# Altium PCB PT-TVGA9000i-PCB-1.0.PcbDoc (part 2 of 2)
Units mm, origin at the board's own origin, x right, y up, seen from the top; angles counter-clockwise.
Board outline 80.1 x 47 mm, 4 copper layers (Top Layer, Layer 1, Layer 2, Bottom Layer), stack 0.603 mm thick; 67 components, 130 nets, 468 pads, 340 vias.
Unrouted connection lines stored in the file: 9.
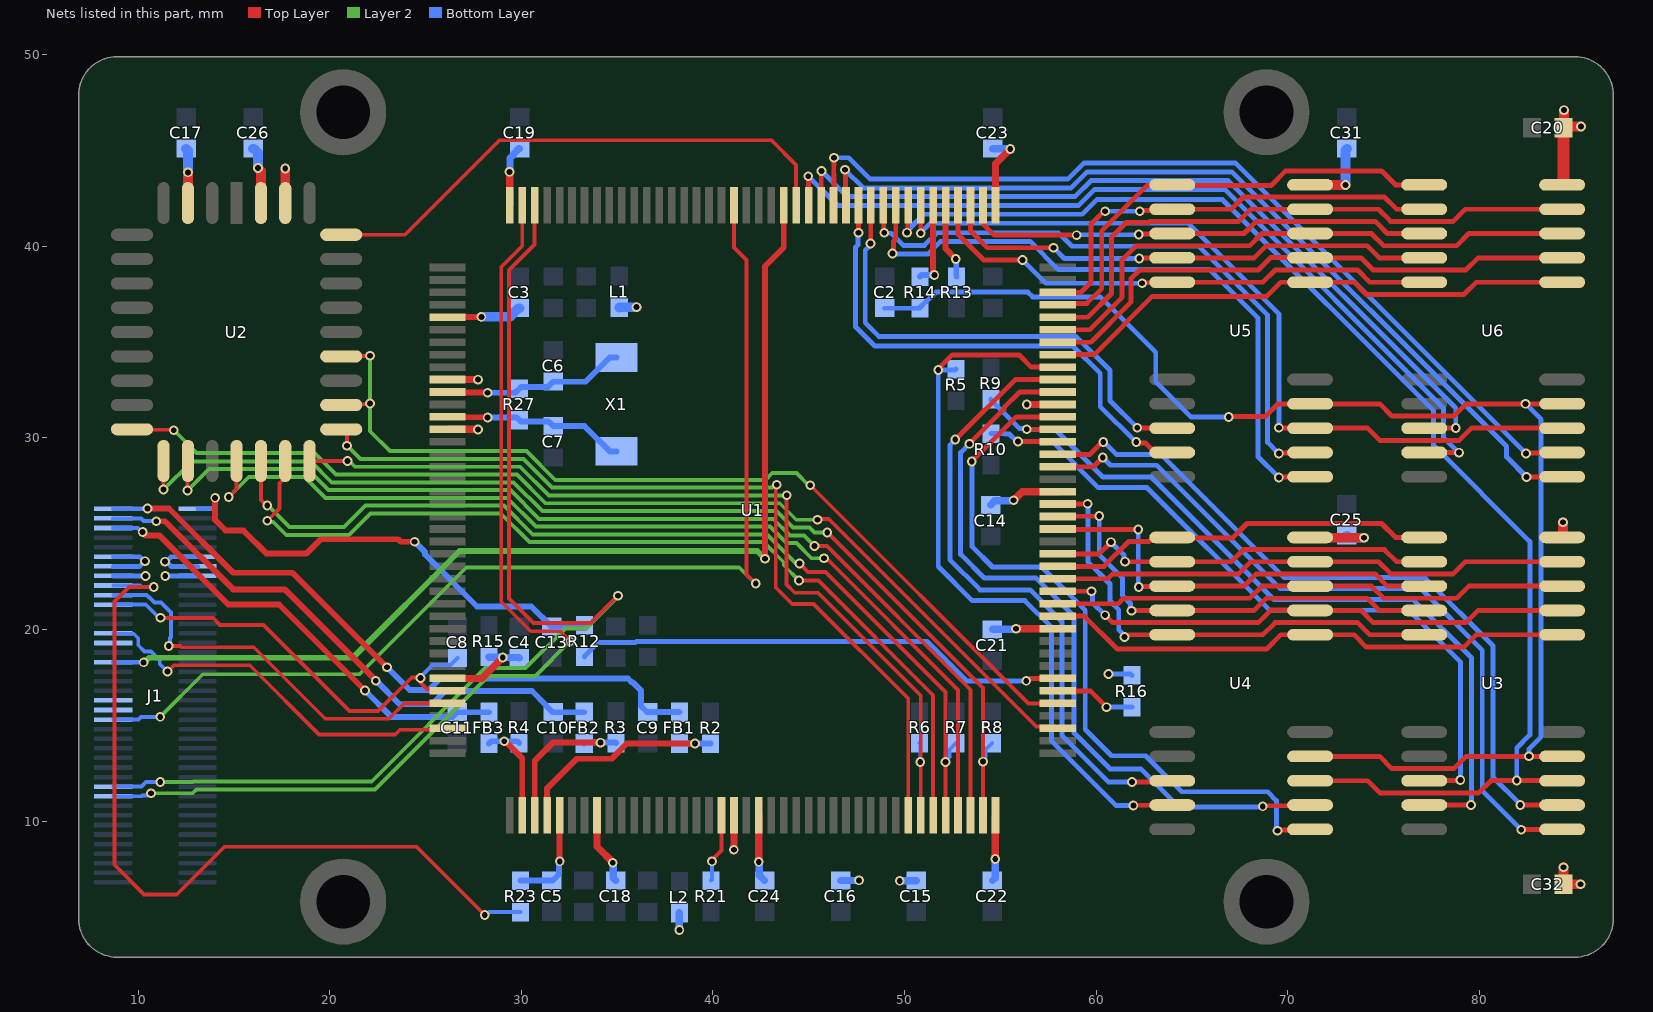
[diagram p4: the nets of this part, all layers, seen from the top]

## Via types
v1: diameter 0.508, hole 0.305, Top Layer to Bottom Layer, tented both sides, 338 vias
v2: diameter 0.7, hole 0.7, Top Layer to Bottom Layer, 2 vias

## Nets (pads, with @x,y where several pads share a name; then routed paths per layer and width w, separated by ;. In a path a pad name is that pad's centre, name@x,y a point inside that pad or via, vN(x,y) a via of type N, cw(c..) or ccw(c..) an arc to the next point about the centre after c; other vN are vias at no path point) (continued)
LA22: J1.21 U1.118 | length 58.4
  Top Layer w0.203: U1.118@30.7,42.15 30.7,40.101 29.362,38.764 29.362,21.618 30.644,20.337 33.621,20.337 v1(35.052,21.768)
  Layer 2 w0.203: v1(11.151,12.04) 12.852,12.04 12.877,12.065 22.197,12.065 28.115,17.983 30.229,17.983 32.299,20.053 33.388,20.053 35.027,21.692 35.027,21.742 v1(35.052,21.768)
  Bottom Layer w0.203: J1.21@8.7,11.8 10.181,11.8 10.42,12.04 v1(11.151,12.04)
LA23: J1.19 U1.119 | length 52.8
  Top Layer w0.203: U1.119@30.05,42.15 30.05,40.026 28.956,38.932 28.956,21.45 30.492,19.914 32.032,19.914 v1(32.552,19.393)
  Layer 2 w0.203: v1(10.668,11.453) 12.84,11.453 13.046,11.659 22.365,11.659 28.283,17.577 30.736,17.577 v1(32.552,19.393)
  Bottom Layer w0.203: J1.19@8.7,11.3 10.189,11.3 10.217,11.328 10.46,11.328 10.586,11.453 v1(10.668,11.453)
MAA0: U1.52 U3.6 U4.6 | length 27.9
  Top Layer w0.254: U1.52@58,20.7 59.397,20.7 61.112,18.985 68.91,18.985 69.654,19.728 U4.6@71.177,19.728 73.475,19.728 74.117,19.086 79.197,19.086 79.839,19.728 U3.6@84.334,19.728
MAA1: U1.54 U3.7 U4.7 | length 28.1
  Top Layer w0.254: U1.54@58,22 58.002,21.998 59.764,21.998 v1(59.766,21.996) ; v1(60.477,20.752) 60.866,20.363 68.46,20.363 69.113,21.017 71.159,21.017 U4.7@71.177,20.998 73.831,20.998 74.466,20.363 79.308,20.363 79.943,20.998 U3.7@84.334,20.998
  Bottom Layer w0.254: v1(59.766,21.996) 59.815,21.948 59.815,21.414 v1(60.477,20.752)
MAA2: U1.53 U3.8 U4.8 | length 27.2
  Top Layer w0.254: U1.53@58,21.35 61.152,21.35 61.435,21.633 68.028,21.633 68.663,22.268 U4.8@71.177,22.268 74.378,22.268 75.013,21.633 78.826,21.633 79.461,22.268 U3.8@84.334,22.268
MAA3: U1.55 U3.9 U4.9 | length 27.2
  Top Layer w0.254: U1.55@58,22.65 60.623,22.65 60.876,22.903 67.444,22.903 68.079,23.538 U4.9@71.177,23.538 74.745,23.538 75.38,22.903 78.645,22.903 79.28,23.538 U3.9@84.334,23.538
MAA4: U1.56 U3.11 U4.11 | length 20.3
  Top Layer w0.254: U1.56@58,23.3 60.409,23.3 61.697,24.587 62.765,24.587 62.986,24.808 U4.11@63.977,24.808 ; U4.11@64.01,24.776 67.118,24.776 67.88,25.538 74.905,25.538 75.634,24.808 U3.11@77.134,24.808
MAA5: U1.57 U3.12 U4.12 | length 20.5
  Top Layer w0.254: U1.57@58,23.95 60.17,23.95 v1(60.782,24.562) ; v1(61.519,23.546) 61.526,23.538 U4.12@63.977,23.538 67.066,23.538 67.701,24.173 75.056,24.173 75.691,23.538 U3.12@77.134,23.538
  Bottom Layer w0.254: v1(60.782,24.562) 61.47,23.874 61.47,23.594 v1(61.519,23.546)
MAA6: U1.59 U3.13 U4.13 | length 22.7
  Top Layer w0.254: U1.59@58,25.25 58.028,25.222 v1(62.205,25.222) ; v1(62.23,22.225) 62.252,22.247 63.956,22.247 U4.13@63.977,22.268 67.723,22.268 68.358,22.903 74.567,22.903 75.202,22.268 U3.13@77.134,22.268
  Bottom Layer w0.254: v1(62.205,25.222) 62.205,22.25 v1(62.23,22.225)
MAA7: U1.60 U3.14 U4.14 | length 23.7
  Top Layer w0.254: U1.60@58,25.9 58.017,25.917 60.156,25.917 v1(60.173,25.933) ; v1(61.849,20.98) 61.858,20.989 63.968,20.989 U4.14@63.977,20.998 68.257,20.998 68.892,21.633 74.161,21.633 74.796,20.998 U3.14@77.134,20.998
  Bottom Layer w0.254: v1(60.173,25.933) 60.173,23.901 61.392,22.682 61.392,21.768 61.8,21.359 61.8,21.029 v1(61.849,20.98)
MAA8: U1.61 U3.15 U4.15 | length 25.5
  Top Layer w0.254: U1.61@58,26.55 58.009,26.559 59.554,26.559 v1(59.563,26.568) ; v1(61.493,19.609) 61.562,19.609 61.682,19.728 U4.15@63.977,19.728 68.714,19.728 69.349,20.363 73.653,20.363 74.288,19.728 U3.15@77.134,19.728
  Bottom Layer w0.254: v1(59.563,26.568) 59.588,26.543 59.588,23.52 60.731,22.377 60.731,21.488 61.189,21.031 61.189,19.982 61.493,19.678 v1(61.493,19.609)
MAB0: U1.73 U5.6 U6.6 | length 28.4
  Top Layer w0.254: U1.73@58,34.35 59.902,34.35 62.941,37.389 68.91,37.389 69.654,38.132 U5.6@71.177,38.132 73.475,38.132 74.117,37.49 79.197,37.49 79.839,38.132 U6.6@84.334,38.132
MAB1: U1.74 U5.7 U6.7 | length 29.4
  Top Layer w0.254: U1.74@58,35 59.74,35 61.824,37.084 61.824,38.317 62.274,38.767 68.46,38.767 69.113,39.421 71.159,39.421 U5.7@71.177,39.402 73.831,39.402 74.466,38.767 79.308,38.767 79.943,39.402 U6.7@84.334,39.402
MAB2: U1.75 U5.8 U6.8 | length 30.1
  Top Layer w0.254: U1.75@58,35.65 59.665,35.65 61.366,37.352 61.366,39.307 62.097,40.037 68.028,40.037 68.663,40.672 U5.8@71.177,40.672 74.378,40.672 75.013,40.037 78.826,40.037 79.461,40.672 U6.8@84.334,40.672
MAB3: U1.76 U5.9 U6.9 | length 30.9
  Top Layer w0.254: U1.76@58,36.3 59.566,36.3 60.808,37.541 60.808,40.488 61.57,41.25 62.761,41.25 62.819,41.307 67.444,41.307 68.079,41.942 U5.9@71.177,41.942 74.745,41.942 75.38,41.307 78.645,41.307 79.28,41.942 U6.9@84.334,41.942
MAB4: U1.77 U5.11 U6.11 | length 24.1
  Top Layer w0.254: U1.77@58,36.95 58.073,37.023 59.527,37.023 60.3,37.795 60.3,40.818 62.657,43.175 63.94,43.175 U5.11@63.977,43.212 64.01,43.18 69.139,43.18 69.901,43.942 74.905,43.942 75.634,43.212 U6.11@77.134,43.212
MAB5: U1.78 U5.12 U6.12 | length 23.2
  Top Layer w0.254: U1.78@58,37.6 59.215,37.6 59.741,38.125 59.741,41.173 59.993,41.426 60.001,41.426 60.409,41.834 v1(60.477,41.834) ; v1(62.281,41.834) 62.329,41.882 63.917,41.882 U5.12@63.977,41.942 67.066,41.942 67.701,42.577 75.056,42.577 75.691,41.942 U6.12@77.134,41.942
  Bottom Layer w0.254: v1(60.477,41.834) v1(62.281,41.834)
MAB6: U1.82 U5.13 U6.13 | length 24.8
  Top Layer w0.254: U1.82@54.1,42.15 54.173,42.077 54.173,41.11 54.694,40.589 v1(58.989,40.589) ; v1(62.23,40.622) 62.255,40.647 63.952,40.647 U5.13@63.977,40.672 67.723,40.672 68.358,41.307 74.567,41.307 75.202,40.672 U6.13@77.134,40.672
  Bottom Layer w0.254: v1(58.989,40.589) 59.005,40.605 62.214,40.605 v1(62.23,40.622)
MAB7: U1.83 U5.14 U6.14 | length 26.2
  Top Layer w0.254: U1.83@53.45,42.15 53.45,40.809 54.331,39.929 v1(57.785,39.929) ; v1(62.255,39.37) 62.272,39.386 63.961,39.386 U5.14@63.977,39.402 68.257,39.402 68.892,40.037 74.161,40.037 74.796,39.402 U6.14@77.134,39.402
  Bottom Layer w0.254: v1(57.785,39.929) 58.344,39.37 v1(62.255,39.37)
MAB8: U1.84 U5.15 U6.15 | length 27.4
  Top Layer w0.254: U1.84@52.8,42.15 52.8,40.621 54.127,39.294 v1(56.159,39.294) ; v1(62.408,38.075) 62.437,38.104 63.948,38.104 U5.15@63.977,38.132 68.714,38.132 69.349,38.767 73.653,38.767 74.288,38.132 U6.15@77.134,38.132
  Bottom Layer w0.254: v1(56.159,39.294) 57.379,38.075 v1@62.382,38.075
MCS16#: J1.35 U1.102 | length 57.4
  Top Layer w0.203: U1.102@41.1,42.15 41.1,39.951 41.758,39.294 41.758,22.884 v1(42.24,22.403) v1(42.24,22.403)
  Layer 2 w0.203: v1(11.151,15.443) 13.373,17.665 21.553,17.665 27.129,23.241 41.377,23.241 42.215,22.403 v1(42.24,22.403)
  Bottom Layer w0.203: J1.35@8.7,15.3 10.011,15.3 10.154,15.443 v1(11.151,15.443)
MD0: U1.64 U3.1 | length 38.9
  Top Layer w0.254: U1.64@58,28.5 59.869,28.5 v1(60.35,28.981) ; v1(82.194,9.55) 82.203,9.559 84.325,9.559 U3.1@84.334,9.568
  Bottom Layer w0.254: v1(60.35,28.981) 60.757,28.575 63.17,28.575 69.596,22.149 76.937,22.149 80.162,18.923 80.162,11.582 v1(82.194,9.55)
MD1: U1.65 U3.2 | length 38.5
  Top Layer w0.254: U1.65@58,29.15 58.008,29.142 59.685,29.142 60.337,29.794 v1(60.376,29.794) ; v1(82.144,10.846) 82.147,10.842 84.331,10.842 U3.2@84.334,10.838
  Bottom Layer w0.254: v1(60.376,29.794) 60.412,29.794 61.072,29.134 63.401,29.134 69.827,22.708 77.168,22.708 80.721,19.154 80.721,12.294 82.144,10.871 v1(82.144,10.846)
MD2: R10.1 U1.66 U3.18 | length 39.6
  Top Layer w0.254: v1(55.931,29.82) 55.941,29.81 57.99,29.81 U1.66@58,29.8 ; U3.18@77.134,12.108 77.151,12.125 79.003,12.125 v1(79.019,12.141)
  Bottom Layer w0.254: R10.1@54.508,30.226 55.22,30.226 55.24,30.206 55.476,30.206 55.862,29.82 v1(55.931,29.82) 57.709,29.82 60.12,27.409 62.66,27.409 69.061,21.008 76.325,21.008 79.019,18.313 v1(79.019,12.141)
MD3: R9.1 U1.67 U3.19 | length 42.5
  Top Layer w0.254: v1(56.388,30.455) 56.39,30.452 57.998,30.452 U1.67@58,30.45 ; U3.19@77.134,10.838 77.138,10.842 79.575,10.842 v1(79.578,10.846)
  Bottom Layer w0.254: R9.1@54.508,32.026 54.508,31.988 55.993,30.503 56.339,30.503 v1(56.388,30.455) 57.861,30.455 60.35,27.965 62.89,27.965 69.291,21.565 76.556,21.565 79.604,18.517 79.604,10.871 v1(79.578,10.846)
MD4: U1.68 U4.1 | length 38.3
  Top Layer w0.254: v1(53.518,28.778) 55.84,31.1 U1.68@58,31.1 ; v1(69.469,9.5) 69.503,9.534 71.143,9.534 U4.1@71.177,9.568
  Bottom Layer w0.254: v1(53.518,28.778) 53.518,24.345 54.596,23.266 57.175,23.266 59.436,21.006 59.436,14.783 60.808,13.411 62.586,13.411 64.465,11.532 68.961,11.532 69.418,11.074 69.418,9.779 69.42,9.777 69.42,9.548 v1(69.469,9.5)
MD5: U1.70 U4.2 | length 39
  Top Layer w0.254: v1(53.391,29.693) 55.194,31.496 55.194,31.572 56.022,32.4 U1.70@58,32.4 ; v1(68.707,10.77) 68.741,10.804 71.143,10.804 U4.2@71.177,10.838
  Bottom Layer w0.254: v1(53.391,29.693) 52.934,29.235 52.934,23.927 54.178,22.682 56.871,22.682 58.852,20.701 58.852,14.605 60.731,12.725 62.332,12.725 64.313,10.744 68.682,10.744 v1(68.707,10.77)
MD6: U1.71 U4.18 | length 33
  Top Layer w0.254: v1(52.654,29.921) 55.783,33.05 U1.71@58,33.05 ; v1(61.874,12.04) 62.762,12.04 ; 62.763,12.04 63.909,12.04 U4.18@63.977,12.108
  Bottom Layer w0.254: v1(52.654,29.921) 52.654,29.896 52.375,29.616 52.375,23.647 53.95,22.073 56.566,22.073 58.217,20.422 58.217,14.478 60.655,12.04 v1(61.874,12.04)
MD7: R5.1 U1.72 U4.19 | length 38.9
  Top Layer w0.254: v1(51.765,33.553) 51.765,33.604 52.502,34.341 55.982,34.341 56.622,33.7 U1.72@58,33.7 ; v1(61.951,10.82) 61.96,10.829 63.968,10.829 U4.19@63.977,10.838
  Bottom Layer w0.254: R5.1@52.7,33.6 52.653,33.553 v1(51.765,33.553) 51.765,23.292 53.543,21.514 56.286,21.514 57.683,20.117 57.683,14.173 61.036,10.82 v1(61.951,10.82)
MD16: U1.89 U5.1 | length 34
  Top Layer w0.254: v1(49.378,39.624) 49.423,39.669 49.423,40.259 49.55,40.386 U1.89@49.55,42.15 ; v1(69.545,27.94) 69.561,27.956 71.161,27.956 U5.1@71.177,27.972
  Bottom Layer w0.254: v1(49.378,39.624) 49.403,39.599 51.232,39.599 51.892,40.259 56.566,40.259 58.039,38.786 65.941,38.786 68.453,36.273 68.453,29.032 v1(69.545,27.94)
MD17: U1.90 U5.2 | length 32.9
  Top Layer w0.254: U1.90@48.9,42.15 48.923,42.127 48.923,40.739 v1(48.946,40.716) ; v1(69.545,29.185) 69.574,29.214 71.148,29.214 U5.2@71.177,29.242
  Bottom Layer w0.254: v1(48.946,40.716) 48.976,40.686 49.306,40.686 49.936,40.056 51.042,40.056 51.703,40.716 58.036,40.716 58.747,40.005 65.368,40.005 68.961,36.412 68.961,29.769 v1(69.545,29.185)
MD18: U1.91 U5.18 | length 25.5
  Top Layer w0.254: v1(48.235,40.157) 48.242,40.165 48.242,42.142 U1.91@48.25,42.15 ; v1(62.154,30.531) 62.163,30.522 63.968,30.522 U5.18@63.977,30.512
  Bottom Layer w0.254: v1(48.235,40.157) 48.235,40.089 47.955,39.809 47.955,36.017 48.666,35.306 58.953,35.306 60.731,33.528 60.731,31.953 v1(62.154,30.531)
MD19: U1.92 U5.19 | length 26.7
  Top Layer w0.254: v1(47.6,40.716) U1.92@47.6,42.15 ; v1(62.103,29.794) 62.152,29.746 62.579,29.746 63.082,29.242 U5.19@63.977,29.242
  Bottom Layer w0.254: v1(47.6,40.716) 47.581,40.697 47.581,40.081 47.447,39.948 47.447,35.814 48.463,34.798 58.801,34.798 60.223,33.376 60.223,31.635 62.064,29.794 v1(62.103,29.794)
MD20: U1.93 U6.1 | length 46.8
  Top Layer w0.254: v1(46.894,43.999) 46.922,43.971 46.922,42.689 47.07,42.541 U1.93@47.07,42.418 ; v1(82.474,27.965) 82.477,27.969 84.331,27.969 U6.1@84.334,27.972
  Bottom Layer w0.254: v1(46.894,43.999) 47.84,43.053 58.711,43.053 59.549,43.891 67.095,43.891 81.432,29.554 81.432,29.007 v1(82.474,27.965)
MD21: U1.94 U6.2 | length 47.6
  Top Layer w0.254: U1.94@46.3,42.15 46.315,42.165 46.315,43.752 46.31,43.757 46.31,44.241 46.315,44.245 46.315,44.613 v1(46.33,44.628) ; v1(82.448,29.185) 82.477,29.214 84.305,29.214 U6.2@84.334,29.242
  Bottom Layer w0.254: v1(46.33,44.628) 47.092,44.628 48.209,43.51 58.522,43.51 59.36,44.348 67.285,44.348 v1(82.448,29.185)
MD22: U1.95 U6.18 | length 43.4
  Top Layer w0.254: U1.95@45.65,42.15 45.66,42.16 45.66,43.932 v1(45.669,43.942) ; U6.18@77.134,30.512 77.138,30.516 78.773,30.516 v1(78.777,30.519)
  Bottom Layer w0.254: v1(45.669,43.942) 47.015,42.596 58.9,42.596 59.739,43.434 66.906,43.434 78.777,31.563 v1(78.777,30.519)
MD23: U1.96 U6.19 | length 44.8
  Top Layer w0.254: v1(44.983,43.663) 44.992,43.654 44.992,42.158 U1.96@45,42.15 ; U6.19@77.134,29.242 77.138,29.239 78.94,29.239 v1(78.943,29.235)
  Bottom Layer w0.254: v1(44.983,43.663) 46.507,42.139 59.09,42.139 59.928,42.977 66.716,42.977 78.13,31.563 78.13,30.048 v1(78.943,29.235)
MEMR#: J1.39
MEMW#: J1.37
MONITOR: R16.1 U1.46 | length 4.2
  Top Layer w0.254: U1.46@58,16.8 59.705,16.8 v1(60.554,15.951)
  Bottom Layer w0.254: v1(60.554,15.951) R16.1@61.874,15.951
NetC3_2: C3.2 U1.125 | length 4
  Top Layer w0.305: U1.125@26.15,36.3 26.161,36.311 27.904,36.311 v1(27.915,36.322)
  Bottom Layer w0.508: v1(27.915,36.322) 29.416,36.322 29.867,36.773 C3.2@29.905,36.773
NetC4_2: C4.2 R15.1 U1.154 | length 5
  Top Layer w0.381: U1.154@26.15,17.45 27.94,17.45 v1(29.032,18.542)
  Bottom Layer w0.381: R15.1@28.309,18.567 28.322,18.555 29.019,18.555 v1(29.032,18.542) ; v1@29.013,18.542 29.87,18.542 C4.2@29.896,18.516
NetC5_1: C5.1 R23.1 U1.5 | length 5.2
  Top Layer w0.305: U1.5@32,10.3 32.002,10.298 32.002,7.901 v1(32.004,7.899)
  Bottom Layer w0.305: R23.1@29.965,6.9 C5.1@31.6,6.9 31.638,6.9 31.956,7.218 31.956,7.256 31.965,7.265 31.965,7.861 v1(32.004,7.899)
NetC6_2: C6.2 R27.2 U1.131 X1.2 | length 9.6
  Top Layer w0.305: U1.131@26.15,32.4 26.17,32.38 28.225,32.38 v1(28.245,32.36)
  Bottom Layer w0.305: v1(28.245,32.36) 29.682,32.36 29.987,32.664 31.388,32.664 C6.2@31.659,32.935 33.347,32.935 34.614,34.203 X1.2@34.964,34.203
NetC7_2: C7.2 R27.1 U1.133 X1.1 | length 9.6
  Top Layer w0.305: U1.133@26.15,31.1 26.168,31.082 28.227,31.082 v1(28.245,31.064)
  Bottom Layer w0.305: v1(28.245,31.064) 29.767,31.064 29.97,30.861 31.429,30.861 C7.2@31.666,30.624 33.293,30.624 34.614,29.303 X1.1@34.964,29.303
NetR13_2: R13.2 U1.85 | length 4
  Top Layer w0.305: U1.85@52.15,42.15 52.15,39.874 v1(52.68,39.345)
  Bottom Layer w0.305: v1(52.68,39.345) 52.702,39.322 52.702,38.447 R13.2@52.725,38.424
NetR14_2: R14.2 U1.86 | length 4.5
  Top Layer w0.305: U1.86@51.5,42.15 51.5,38.712 51.523,38.689 51.523,38.545 v1(51.562,38.506)
  Bottom Layer w0.305: R14.2@50.813,38.424 50.895,38.506 v1(51.562,38.506)
NetR21_2: R21.2 U1.18 | length 3.6
  Top Layer w0.203: v1(39.954,7.899) 39.954,7.976 40.45,8.471 U1.18@40.45,10.3
  Bottom Layer w0.203: R21.2@39.91,6.9 39.954,6.945 v1(39.954,7.899)
OSC: J1.47 U1.98 | length 55.5
  Top Layer w0.305: v1(42.723,23.698) 42.723,38.964 43.7,39.941 U1.98@43.7,42.15
  Layer 2 w0.305: v1(10.287,18.288) 10.326,18.288 10.567,18.529 21.196,18.529 26.772,24.105 42.316,24.105 v1(42.723,23.698)
  Bottom Layer w0.254: J1.47@8.7,18.3 8.706,18.294 10.281,18.294 v1(10.287,18.288)
RAS*: C2.1 R14.1 U3.4 U4.4 U5.4 U6.4 | length 72.8
  Top Layer w0.254: v1(66.929,31.09) 66.954,31.115 68.834,31.115 69.501,31.782 U5.4@71.177,31.782 74.81,31.782 75.445,31.147 78.682,31.147 79.317,31.782 v1(82.423,31.782) U6.4@84.334,31.782 ; U4.4@71.177,13.378 74.81,13.378 75.445,12.743 78.682,12.743 79.317,13.378 U3.4@84.334,13.378
  Bottom Layer w0.254: C2.1@48.963,36.774 R14.1@50.813,36.773 50.813,36.811 51.13,37.129 51.168,37.129 51.651,37.612 56.445,37.612 56.693,37.363 60.223,37.363 63.119,34.468 63.119,32.944 64.973,31.09 v1(66.929,31.09) ; v1(82.423,31.782) 83.236,30.97 83.236,14.402 82.605,13.771 82.605,13.39 v1(82.601,13.386)
REFSH#: J1.53 U1.158 | length 20.4
  Top Layer w0.203: v1(11.532,17.805) 11.862,18.136 15.824,18.136 19.431,14.529 23.419,14.529 23.659,14.769 26.069,14.769 U1.158@26.15,14.85
  Bottom Layer w0.203: J1.53@8.7,19.8 8.718,19.782 9.769,19.782 10.005,19.546 10.005,19.182 10.34,18.847 10.671,18.847 11.13,18.387 11.13,18.207 v1(11.532,17.805)
RESET: J1.63 R23.2 | length 42.7
  Top Layer w0.203: v1(10.817,22.225) 9.525,22.225 8.763,21.463 8.763,7.722 10.312,6.172 12.014,6.172 14.503,8.661 24.536,8.661 v1(28.092,5.105)
  Bottom Layer w0.203: J1.63@8.7,22.3 10.098,22.3 10.173,22.225 v1(10.817,22.225) ; v1(28.092,5.105) 28.175,5.105 28.318,5.249 R23.2@29.965,5.249
RMD0: U1.43 U2.13 | length 54.8
  Top Layer w0.203: U2.13@9.678,30.45 9.701,30.427 11.839,30.427 v1(11.862,30.404) ; v1(45.466,25.73) 45.517,25.781 46.05,25.781 56.883,14.948 57.902,14.948 U1.43@58,14.85
  Layer 2 w0.203: v1(11.862,30.404) 13.056,29.21 19.202,29.21 20.32,28.092 29.772,28.092 31.27,26.594 43.491,26.594 44.354,25.73 v1(45.466,25.73)
RMD1: R8.1 U1.39 U2.14 | length 57.6
  Top Layer w0.203: v1(11.328,27.305) U2.14@11.329,28.799 ; v1(45.973,25.068) 45.978,25.068 54.1,16.947 U1.39@54.1,10.3
  Layer 2 w0.203: v1(11.328,27.305) 12.802,28.778 19.015,28.778 20.107,27.686 29.603,27.686 31.102,26.187 43.322,26.187 44.186,25.324 45.049,25.324 45.303,25.07 45.971,25.07 v1(45.973,25.068)
  Bottom Layer w0.203: v1(54.102,13.106) 54.242,13.246 54.242,13.729 R8.1@54.585,14.072
RMD2: U1.38 U2.15 | length 54.2
  Top Layer w0.203: v1(12.573,27.254) 12.586,27.267 12.586,28.786 U2.15@12.599,28.799 ; v1(45.31,24.359) 45.951,24.359 53.45,16.86 U1.38@53.45,10.3
  Layer 2 w0.203: v1(12.573,27.254) 13.691,28.372 18.847,28.372 19.939,27.28 29.435,27.28 30.934,25.781 43.154,25.781 44.018,24.917 44.752,24.917 v1(45.31,24.359)
RMD3: U1.37 U2.17 | length 51.6
  Top Layer w0.203: v1(14.732,26.924) 15.139,27.331 U2.17@15.139,28.799 ; v1@45.872,23.774 52.8,16.847 U1.37@52.8,10.3
  Layer 2 w0.203: v1(14.732,26.924) 15.773,27.965 18.678,27.965 19.771,26.873 29.267,26.873 30.765,25.375 42.986,25.375 43.849,24.511 44.368,24.511 45.155,23.724 v1(45.796,23.724)
RMD4: R7.1 U1.36 U2.18 | length 50.5
  Top Layer w0.203: U2.18@16.409,28.799 16.409,26.771 16.71,26.47 v1(16.739,26.47) ; v1(44.526,23.444) 44.958,23.012 45.872,23.012 52.15,16.735 U1.36@52.15,10.3
  Layer 2 w0.203: v1(16.739,26.47) 16.787,26.47 17.907,25.349 20.752,25.349 21.869,26.467 29.098,26.467 30.597,24.968 42.817,24.968 44.283,23.503 44.468,23.503 v1(44.526,23.444)
  Bottom Layer w0.203: v1(52.146,13.081) 52.146,13.132 52.357,13.343 52.357,13.728 R7.1@52.7,14.071
RMD5: U1.35 U2.19 | length 49.3
  Top Layer w0.203: v1(16.739,25.679) 17.374,26.314 17.374,27.635 17.679,27.941 U2.19@17.679,28.799 ; v1(44.501,22.555) 45.517,22.555 51.5,16.572 U1.35@51.5,10.3
  Layer 2 w0.203: v1(16.739,25.679) 16.797,25.621 17.051,25.621 17.729,24.943 21.006,24.943 22.123,26.06 28.93,26.06 30.429,24.562 42.649,24.562 43.698,23.512 43.698,23.358 v1(44.501,22.555)
RMD6: R6.1 U1.34 U2.20 | length 47
  Top Layer w0.203: U2.20@18.949,28.799 v1(20.93,28.799) ; v1(43.859,27.014) 43.847,27.002 43.847,26.465 43.84,26.459 43.84,22.352 44.272,21.92 45.491,21.92 50.85,16.562 U1.34@50.85,10.3
  Layer 2 w0.203: v1(20.93,28.799) 21.01,28.799 21.311,28.499 29.94,28.499 31.439,27 43.845,27 v1(43.859,27.014)
  Bottom Layer w0.203: R6.1@50.787,14.071 50.825,14.033 v1(50.825,13.081)
RMD7: U1.33 U2.21 | length 45.3
  Top Layer w0.203: U2.21@20.6,30.45 20.73,30.45 20.93,30.251 20.904,30.251 v1(20.904,29.591) ; v1(43.332,27.559) 43.282,27.508 43.282,22.2 44.145,21.336 45.263,21.336 50.2,16.399 U1.33@50.2,10.3
  Layer 2 w0.203: v1(20.904,29.591) 20.928,29.591 21.614,28.905 30.108,28.905 31.607,27.407 43.098,27.407 43.25,27.559 v1(43.332,27.559)
ROMA0: U1.97 U2.29 | length 28.4
  Top Layer w0.203: U2.29@20.6,40.61 23.922,40.61 28.854,45.542 43.053,45.542 44.35,44.245 U1.97@44.35,42.15
SMEMR#: C8.1 J1.59 U1.155 | length 23.3
  Top Layer w0.203: v1(11.165,20.614) 11.179,20.599 13.919,20.599 14.275,20.244 16.535,20.244 21.031,15.748 22.53,15.748 24.282,17.501 24.714,17.501 24.773,17.442 24.773,17.214 25.088,16.898 26.052,16.898 U1.155@26.15,16.8
  Bottom Layer w0.203: J1.59@8.7,21.3 10.399,21.3 11.086,20.614 v1(11.165,20.614) ; v1(24.741,17.474) 24.741,17.527 25.362,18.148 26.302,18.148 C8.1@26.67,18.517
SMEMW#: J1.61 U1.156 | length 21.7
  Top Layer w0.203: v1(11.598,19.138) 12.195,19.138 12.258,19.075 16.034,19.075 19.768,15.342 23.082,15.342 23.891,16.15 U1.156@26.15,16.15
  Bottom Layer w0.203: J1.61@8.7,21.8 10.451,21.8 10.545,21.706 10.568,21.706 10.852,21.422 11.192,21.422 11.724,20.89 11.724,19.62 11.656,19.553 11.656,19.197 v1(11.598,19.138)
SYSCLK: J1.51
VCC: C14.1 C15.1 C16.1 C17.1 C18.1 C19.1 C20.1 C21.1 C22.1 C23.1 C24.1 C25.1 C26.1 C31.1 C32.1 J1.65 J1.66 J1.67 J1.68 J1.69 J1.70 L1.2 L2.2 R16.2 U1.8 U1.19 U1.21 U1.40 U1.51 U1.62 U1.69 U1.81 U1.120 U1.130 U1.134 U2.3 U2.31 U2.32 U3.10 U4.10 U5.10 U6.10 | length 69.4
  Top Layer w0.381: U1.130@26.15,33.05 26.152,33.048 27.734,33.048 v1(27.736,33.047) ; U1.134@26.15,30.45 v1@27.734,30.448 ; v1(29.388,43.891) 29.394,43.885 29.394,42.156 U1.120@29.4,42.15 ; U1.8@33.95,10.3 33.95,8.671 34.771,7.85 v1(34.771,7.823) ; v1(41.097,8.509) 41.099,8.51 U1.19@41.1,10.3 U1.19@41.1,10.3 ; v1(42.393,7.874) 42.396,7.878 42.396,10.296 U1.21@42.4,10.3 ; v1(54.737,8.026) 54.744,8.033 54.744,10.293 U1.40@54.75,10.3 ; U1.81@54.75,42.15 54.75,44.311 v1(55.524,45.085) ; v1(55.702,26.746) 56.156,27.2 U1.62@58,27.2 ; v1(55.829,20.041) 55.834,20.045 57.995,20.045 U1.51@58,20.05 ; v1(56.388,31.75) U1.69@58,31.75
  Top Layer w0.508: v1(12.598,43.866) 12.598,42.901 U2.3@12.624,42.875 ; v1(16.256,44.094) 16.409,43.941 U2.32@16.409,42.261 ; U2.31@17.679,42.261 v1(17.678,44.069) ; U4.10@71.177,24.808 71.195,24.79 v1(73.99,24.79) ; U5.10@71.177,43.212 71.184,43.205 v1(73.025,43.205) ; U3.10@84.334,24.808 84.379,24.853 v1(84.379,25.603) ; U6.10@84.334,43.212 84.353,43.212 U6.10@84.4,43.259 ; C32.1@84.4,6.7 84.406,6.706 v1(85.293,6.706) ; C20.1@84.4,46.2 84.453,46.253 v1(85.319,46.253) ; C32.1@84.403,6.703 v1(84.403,7.59) ; C20.1@84.427,46.227 v1(84.427,47.114)
  Top Layer w0.635: U6.10@84.4,43.259 C20.1@84.4,46.2
  Bottom Layer w0.254: J1.65@8.7,22.8 v1(10.389,22.8) ; J1.67@8.7,23.3 10.081,23.3 v1@10.352,23.571 ; J1.69@8.7,23.8 10.081,23.8 10.31,23.571 v1@10.352,23.571 ; v1(10.363,23.571) v1@10.352,23.571 ; v1(11.405,23.546) v1@11.465,23.546 ; v1(11.411,22.8) J1.66@13.1,22.8 ; J1.68@13.1,23.3 11.719,23.3 11.473,23.546 v1@11.465,23.546 ; J1.70@13.1,23.8 11.719,23.8 v1@11.465,23.546 ; v1(60.655,17.678) 61.798,17.678 R16.2@61.874,17.602
  Bottom Layer w0.381: v1(29.388,43.891) 29.412,43.915 29.412,44.601 29.594,44.783 29.594,44.82 29.873,45.1 C19.1@29.911,45.1 ; v1(34.771,7.823) 34.796,7.799 34.796,7.038 C18.1@34.933,6.9 ; v1(38.252,4.318) L2.2@38.253,5.217 ; v1(42.393,7.874) 42.417,7.85 42.417,7.18 42.696,6.9 C24.1@42.7,6.9 ; C16.1@46.665,6.9 46.669,6.904 47.621,6.904 v1(47.625,6.909) ; v1(49.759,6.883) 49.767,6.892 50.621,6.892 C15.1@50.629,6.9 ; C14.1@54.5,26.5 54.722,26.722 55.678,26.722 v1(55.702,26.746) ; C22.1@54.594,6.9 54.737,7.043 v1@54.737,7.992 ; C21.1@54.594,20 54.614,20.02 55.809,20.02 v1(55.829,20.041) ; C23.1@54.6,45.1 54.608,45.093 55.517,45.093 v1(55.524,45.085)
  Bottom Layer w0.508: C17.1@12.5,45.1 12.598,45.002 v1(12.598,43.866) ; C26.1@16,45.1 16.038,45.1 16.254,44.884 16.254,44.096 v1(16.256,44.094) ; L1.2@35.117,36.81 35.137,36.83 v1(36.017,36.83) ; v1(73.025,43.205) 73.025,45.025 C31.1@73.1,45.1 ; C25.1@73.1,24.9 73.21,24.79 v1(73.99,24.79)
  other v1: 27.736,30.447
VGA_B: FB3.2 R4.2 U1.2 | length 6
  Top Layer w0.305: v1(29.108,14.173) 29.159,14.173 30.05,13.282 U1.2@30.05,10.3
  Bottom Layer w0.305: FB3.2@28.308,14.045 28.436,14.173 v1(29.108,14.173) 29.796,14.173 R4.2@29.892,14.077
VGA_B1: C11.1 FB3.1 J1.75 | length 23.8
  Top Layer w0.305: v1(10.236,25.095) 10.236,25.07 10.389,24.917 11.1,24.917 14.707,21.311 17.348,21.311 v1(21.844,16.815)
  Bottom Layer w0.229: J1.75@8.7,25.3 9.973,25.3 10.178,25.095 v1(10.236,25.095)
  Bottom Layer w0.305: v1(21.844,16.815) 23.216,15.443 26.4,15.443 C11.1@26.652,15.696 ; C11.1@26.65,15.697 26.663,15.685 FB3.1@28.308,15.685
VGA_G: FB2.2 R3.2 U1.3 | length 8.4
  Top Layer w0.305: U1.3@30.7,10.3 30.7,13.149 31.648,14.097 v1(34.138,14.097)
  Bottom Layer w0.305: FB2.2@33.281,14.045 33.333,14.097 34.917,14.097 R3.2@34.937,14.077
VGA_G1: C10.1 FB2.1 J1.77 | length 29.4
  Top Layer w0.305: v1(10.947,25.654) 11.405,25.654 14.961,22.098 17.653,22.098 22.401,17.35 v1(22.401,17.324)
  Bottom Layer w0.229: J1.77@8.7,25.8 10.156,25.8 10.289,25.667 10.935,25.667 v1(10.947,25.654)
  Bottom Layer w0.305: v1(22.401,17.324) 22.427,17.324 23.647,16.104 25.349,16.104 26.035,16.789 30.555,16.789 31.304,16.04 31.304,16.013 31.621,15.696 C10.1@31.659,15.696 31.67,15.685 FB2.1@33.281,15.685
VGA_R: FB1.2 R2.2 U1.4 | length 11.7
  Top Layer w0.305: U1.4@31.35,10.3 31.35,11.716 32.893,13.259 34.722,13.259 35.509,14.046 v1(39.065,14.046)
  Bottom Layer w0.305: FB1.2@38.253,14.045 FB1.2@38.253,14.045 v1(39.065,14.046) 39.879,14.046 R2.2@39.884,14.051
VGA_R1: C9.1 FB1.1 J1.79 | length 34.9
  Top Layer w0.305: v1(10.49,26.314) 11.608,26.314 14.961,22.962 18.056,22.962 v1@22.985,18.032
  Bottom Layer w0.229: J1.79@8.7,26.3 10.476,26.3 v1(10.49,26.314)
  Bottom Layer w0.305: v1(22.987,18.034) 24.181,16.84 25.171,16.84 25.781,17.45 35.571,17.45 35.799,17.221 35.85,17.221 36.242,16.83 36.242,16.013 36.559,15.696 38.243,15.696 FB1.1@38.253,15.685
VGA_ROMCS*: U1.45 U2.22 U2.24 | length 49.1
  Top Layer w0.203: U2.22@20.6,31.72 20.639,31.759 22.059,31.759 v1(22.098,31.797) ; U2.24@20.6,34.26 20.615,34.275 22.083,34.275 v1(22.098,34.29) ; v1(45.085,27.534) 56.469,16.15 U1.45@58,16.15
  Layer 2 w0.203: v1(22.098,34.29) v1(22.098,31.797) 22.098,30.353 23.139,29.312 30.277,29.312 31.775,27.813 42.745,27.813 43.101,28.169 44.368,28.169 45.003,27.534 v1(45.085,27.534)
VSYNC: R12.1 U1.47 | length 26
  Top Layer w0.254: v1(56.363,17.323) 56.431,17.323 56.559,17.45 U1.47@58,17.45
  Bottom Layer w0.254: R12.1@33.299,18.567 33.299,18.605 34.023,19.329 35.969,19.329 36.02,19.38 51.181,19.38 53.238,17.323 v1(56.363,17.323)
VSYNC1: C13.1 J1.80 R12.2 | length 24.9
  Top Layer w0.305: v1(14.021,26.873) 14.021,25.718 14.568,25.171 15.494,25.171 16.688,23.978 18.796,23.978 19.533,24.714 23.571,24.714 23.698,24.587 v1(24.435,24.587)
  Bottom Layer w0.229: J1.80@13.1,26.3 13.98,26.3 13.986,26.306 13.986,26.838 v1(14.021,26.873)
  Bottom Layer w0.305: v1(24.435,24.587) 24.982,24.04 24.982,23.913 27.686,21.209 30.517,21.209 31.56,20.167 33.248,20.167 R12.2@33.299,20.218
WE0*: U1.88 U3.3 U4.3 | length 69.6
  Top Layer w0.254: v1(50.14,40.718) 50.17,40.748 50.17,42.12 U1.88@50.2,42.15 ; U4.3@71.177,12.108 74.175,12.108 74.81,11.473 79.977,11.473 80.62,12.116 v1(81.966,12.116) 81.969,12.112 84.331,12.112 U3.3@84.334,12.108
  Bottom Layer w0.254: v1(50.14,40.718) 50.14,40.787 50.267,40.913 50.267,40.933 51.015,41.681 59.279,41.681 60.041,42.443 66.603,42.443 77.622,31.424 77.622,29.616 82.652,24.587 82.652,14.503 81.966,13.818 v1(81.966,12.116)
WE2*: U1.87 U5.3 U6.3 | length 43.6
  Top Layer w0.254: v1(50.851,40.691) U1.87@50.85,42.15 ; v1(69.545,30.531) 69.554,30.522 71.168,30.522 U5.3@71.177,30.512 74.175,30.512 74.81,29.877 78.961,29.877 79.596,30.512 U6.3@84.334,30.512
  Bottom Layer w0.254: v1(50.851,40.691) 50.851,40.716 51.34,41.206 64.814,41.206 69.545,36.474 v1(69.545,30.531)
pads on no net: J1.62 J1.64 J1.76 U1.9 U1.10 U1.11 U1.12 U1.14 U1.15 U1.16 U1.17 U1.20 U1.24 U1.44 U1.63 U1.100 U1.111 U1.112 U1.123 U1.127 U1.129 U1.132 U1.159 U2.1 U2.2 U2.30 U3.5 U4.5 U5.5 U6.5

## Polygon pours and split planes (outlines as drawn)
GND on Layer 1 "NONET_L-01_P-001" (solid, remove dead copper, pour order 0): 6.9,4.9 6.9,47.9 cw(c8.9,47.9) 8.9,49.9 85,49.9 cw(c85,47.9) 87,47.9 87,4.9 cw(c85,4.9) 85,2.9 8.9,2.9 cw(c8.9,4.9)
GND on Bottom Layer "NONET_L-01_P-001" (solid, remove dead copper, pour order 2): 6.9,4.9 6.9,47.9 cw(c8.9,47.9) 8.9,49.9 85,49.9 cw(c85,47.9) 87,47.9 87,4.9 cw(c85,4.9) 85,2.9 8.9,2.9 cw(c8.9,4.9)
GND on Top Layer "NONET_L-01_P-001" (solid, remove dead copper, pour order 3): 6.9,4.9 6.9,47.9 cw(c8.9,47.9) 8.9,49.9 85,49.9 cw(c85,47.9) 87,47.9 87,4.9 cw(c85,4.9) 85,2.9 8.9,2.9 cw(c8.9,4.9)
VCC on Layer 2 "NONET_L-01_P-001" (solid, remove dead copper, pour order 1): 6.9,4.9 6.9,47.9 cw(c8.9,47.9) 8.9,49.9 85,49.9 cw(c85,47.9) 87,47.9 87,4.9 cw(c85,4.9) 85,2.9 8.9,2.9 cw(c8.9,4.9)

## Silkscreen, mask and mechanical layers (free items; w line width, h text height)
Top Overlay:
  text "Trident" at 8.073,9.726 h3.56
  text "Rev 1.1" at 7.976,3.81 h1.2
Bottom Overlay:
  lines w0.203: 74.5,2.9 74.5,49.9
Mechanical 1:
  the board outline again, w0.203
